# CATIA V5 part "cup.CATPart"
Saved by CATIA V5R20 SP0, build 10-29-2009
Part number: 保温杯
Material "Grey Sky"
Bounding box of the stored display mesh (mm): x -45 to 60, y -44.889 to 44.889, z 0 to 269
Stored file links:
  E:\设计\180212313林恺昇\cup.CATPart
  C:\Program Files\Dassault Systemes\B20\intel_a\startup\materials\Catalog.CATMaterial
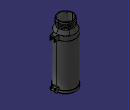
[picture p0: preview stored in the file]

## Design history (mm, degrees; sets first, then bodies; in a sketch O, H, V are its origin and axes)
Body1 (main body)
  Sketch1 on xy-plane, origin (0, 0, 0), H (1, 0, 0), V (0, 1, 0)
    circle A1 centre (0, 0) radius 45
    radius A1 = 45
  Pad1: profile Sketch1, direction (0, 0, 1), length 15
  Fillet1: radius 5, on edge [start face of Pad1 | face of Pad1 from Sketch1.A1]
  Sketch2 on xy-plane, origin (0, 0, 0), H (1, 0, 0), V (0, 1, 0)
    circle A1 centre (0, 0) radius 29.5
    radius A1 = 29.5
  Shell1: ExtOffset 0, Face end face of Pad1, IntOffset 3
  Pocket1: profile Sketch2, direction (0, 0, 1), length 1.5
  Fillet2: radius 0.75, on edge [face of Pocket1 from Sketch2.A1 | start face of Pad1]
  Fillet3: radius 0.75, on edge [end face of Pocket1 | face of Pocket1 from Sketch2.A1]
  Body2
    Sketch3 on Plane1, origin (0, 0, 14), H (1, 0, 0), V (0, 1, 0)
      line L1 (41.3068, 10) -> (60, 10)
      line L2 (60, 10) -> (60, -10)
      line L3 (60, -10) -> (41.3068, -10)
      arc A1 centre (0, 0) radius 42.5 from (41.3068, -10) to (41.3068, 10) ccw
      length L2 = 20
      distance L3 O = 10
      distance L2 O = 60
      radius A1 = 42.5
      horizontal: L1 H, L3 H
      vertical: L2 V
    Pad2: profile Sketch3, direction (0, 0, 1), length 10, mirrored extent
    Fillet4: radius 2, on edge [face of Pad2 from Sketch3.L2 | end face of Pad2]
    Sketch4 on end face of Pad2, origin (0, 0, 24), H (1, 0, 0), V (0, 1, 0)
      line L1 (47, 7.5) -> (64, 7.5)
      line L2 (64, 7.5) -> (64, -7.5)
      line L3 (64, -7.5) -> (47, -7.5)
      line L4 (47, -7.5) -> (47, 7.5)
      length L3 = 17
      length L2 = 15
      distance O L3 = 7.5
      distance L4 O = 47
      horizontal: L1 H, L3 H
      vertical: L2 V, L4 V
    Pocket2: profile Sketch4, direction (0, 0, -1), length 9
    Sketch5 on face of Pad2 from Sketch3.L3, origin (0, -10, 0), H (1, 0, 0), V (0, 0, 1)
      circle A1 centre (55, 19) radius 2.5
      point P1 (55, 19)
      reference projected line E1 (35, 24) -> (60, 24) from edge [face of Pad2 from Sketch3.L3 | end face of Pad2]
      radius A1 = 2.5
      distance P1 V = 55
      distance P1 E1 = 5
    Pocket3: profile Sketch5, direction (0, 1, 0), length 22
    Fillet5: radius 14, on edge [start face of Pad2 | face of Pad2 from Sketch3.L2]
  Assemble1: tool Body2
Body3
  Plane1: type Offset, RefPlane xy-plane, Offset 14
  Sketch6 on Plane1, origin (0, 0, 14), H (1, 0, 0), V (0, 1, 0)
    circle A1 centre (0, 0) radius 42.5
    radius A1 = 42.5
  Pad3: profile Sketch6, direction (0, 0, 1), length 190
  Plane2: type Offset, RefPlane Plane1, Offset 190
  Body4
    Sketch7 on Plane2, origin (0, 0, 204), H (1, 0, 0), V (0, 1, 0)
      circle A1 centre (0, 0) radius 41.75
      radius A1 = 41.75
    Pad4: profile Sketch7, direction (0, 0, 1), length 20
  Assemble2: tool Body4
  Plane3: type Offset, RefPlane face of Pad4, Offset 5, reversed
  Sketch8 on Plane3, origin (0, 0, 229), H (1, 0, 0), V (0, -1, 0)
    circle A1 centre (0, 0) radius 37.5
    radius A1 = 37.5
  Plane4: type Offset, RefPlane Plane3, Offset 5, reversed
  Plane5: type Offset, RefPlane Plane4, Offset 5, reversed
  Plane6: type Offset, RefPlane Plane5, Offset 30, reversed
  Sketch9 on face of Pad4, origin (0, 0, 224), H (1, 0, 0), V (0, 1, 0)
    circle A1 centre (0, 0) radius 41.5
    radius A1 = 41.5
  Sketch10 on Plane4, origin (0, 0, 234), H (1, 0, 0), V (0, -1, 0)
    circle A1 centre (0, 0) radius 35
    point P1 (35, 0)
    radius A1 = 35
    coincidence: A1 P1, P1 H
  Sketch11 on Plane5, origin (0, 0, 239), H (1, 0, 0), V (0, -1, 0)
    circle A1 centre (0, 0) radius 32.5
    radius A1 = 32.5
  Sketch12 on Plane6, origin (0, 0, 269), H (1, 0, 0), V (0, -1, 0)
    circle A1 centre (0, 0) radius 32.5
    point P1 (32.5, 0)
    radius A1 = 32.5
    coincidence: A1 P1, P1 H
  Loft1: solid, Sections (Sketch9; Sketch8; Sketch10; Sketch11; Sketch12)
  Shell2: ExtOffset 0, Face face of Loft1, IntOffset 3
  Body5
    Sketch13 on Plane2, origin (0, 0, 204), H (1, 0, 0), V (0, 1, 0)
      line L1 (40.2772, 10) -> (60, 10)
      line L2 (60, 10) -> (60, -10)
      arc A1 centre (0, 0) radius 41.5 from (40.2772, -10) to (40.2772, 10) ccw
      line L3 (40.2772, -10) -> (60, -10)
      length L2 = 20
      distance L2 O = 60
      distance L1 O = 10
      radius A1 = 41.5
      horizontal: L1 H, L3 H
      vertical: L2 V
    Pad5: profile Sketch13, direction (0, 0, 1), length 20
    Sketch14 on face of Pad4, origin (0, 0, 204), H (1, 0, 0), V (0, -1, 0)
      line L1 (47, 7.5) -> (64, 7.5)
      line L2 (64, 7.5) -> (64, -7.5)
      line L3 (64, -7.5) -> (47, -7.5)
      line L4 (47, -7.5) -> (47, 7.5)
      distance O L4 = 47
      length L2 = 15
      length L3 = 17
      distance O L3 = 7.5
      horizontal: L1 H, L3 H
      vertical: L2 V, L4 V
    Pocket4: profile Sketch14, direction (0, 0, 1), length 18
    Sketch15 on face of Pad5 from Sketch13.L3, origin (0, -10, 0), H (1, 0, 0), V (0, 0, 1)
      circle A1 centre (55, 211) radius 2.5
      point P1 (55, 211)
      reference projected line E1 (40.2772, 224) -> (60, 224) from edge [face of Pad5 from Sketch13.L3 | end face of Pad5]
      radius A1 = 2.5
      distance P1 V = 55
      distance P1 E1 = 13
    Pocket5: profile Sketch15, direction (0, 1, 0), length 24
    Point1: type OnSurface, Support face of Loft1, Length 26.546, Direction (0.9031, 0.3977, -0.1619)
    Helix1: Direction Z axis, RefPoint Point1, Pitch 5, Height 24, TaperAngle 0
    Line1: type PtDir, RefPoint Point1, Direction (1, 0, 0), Start 0, End 20
    Point2: type OnCurve, Support Helix1, Length 17.591
    Connect1: Curve1 Helix1, Point1 Point2, Tension1 1, Curve2 Line1, Point2 vertex of Line1, Tension2 1
    Plane7: type Normal, Curve Connect1, RefPoint vertex of Connect1
    Line2: type PtDir, RefPoint vertex of Helix1, Direction (0, 1, 0), Start 0, End 20
    Point3: type OnCurve, Support Connect1, Length 977.959
    Connect2: Curve1 Line2, Point1 vertex of Line2, Tension1 1, Curve2 Connect1, Point2 Point3, Tension2 1
    Circle1: type CtrRad, Start 0, End 180, Center vertex of Connect1, Support Plane7, Radius 1.5, FirstDirection (0, 1, 0)
    Rib1: profile Circle1, centre curve Connect2
    Body6
      Sketch16 on face of Loft1, origin (0, 0, 269), H (1, 0, 0), V (0, 1, 0)
        circle A1 centre (0, 0) radius 29.5
        radius A1 = 29.5
      Pad6: profile Sketch16, direction (0, 0, -1), length 33
    Remove1: tool Body6
    Fillet6: radius 3, on edge [face of Pad5 from Sketch13.L2 | end face of Pad5]
  Assemble3: tool Body5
